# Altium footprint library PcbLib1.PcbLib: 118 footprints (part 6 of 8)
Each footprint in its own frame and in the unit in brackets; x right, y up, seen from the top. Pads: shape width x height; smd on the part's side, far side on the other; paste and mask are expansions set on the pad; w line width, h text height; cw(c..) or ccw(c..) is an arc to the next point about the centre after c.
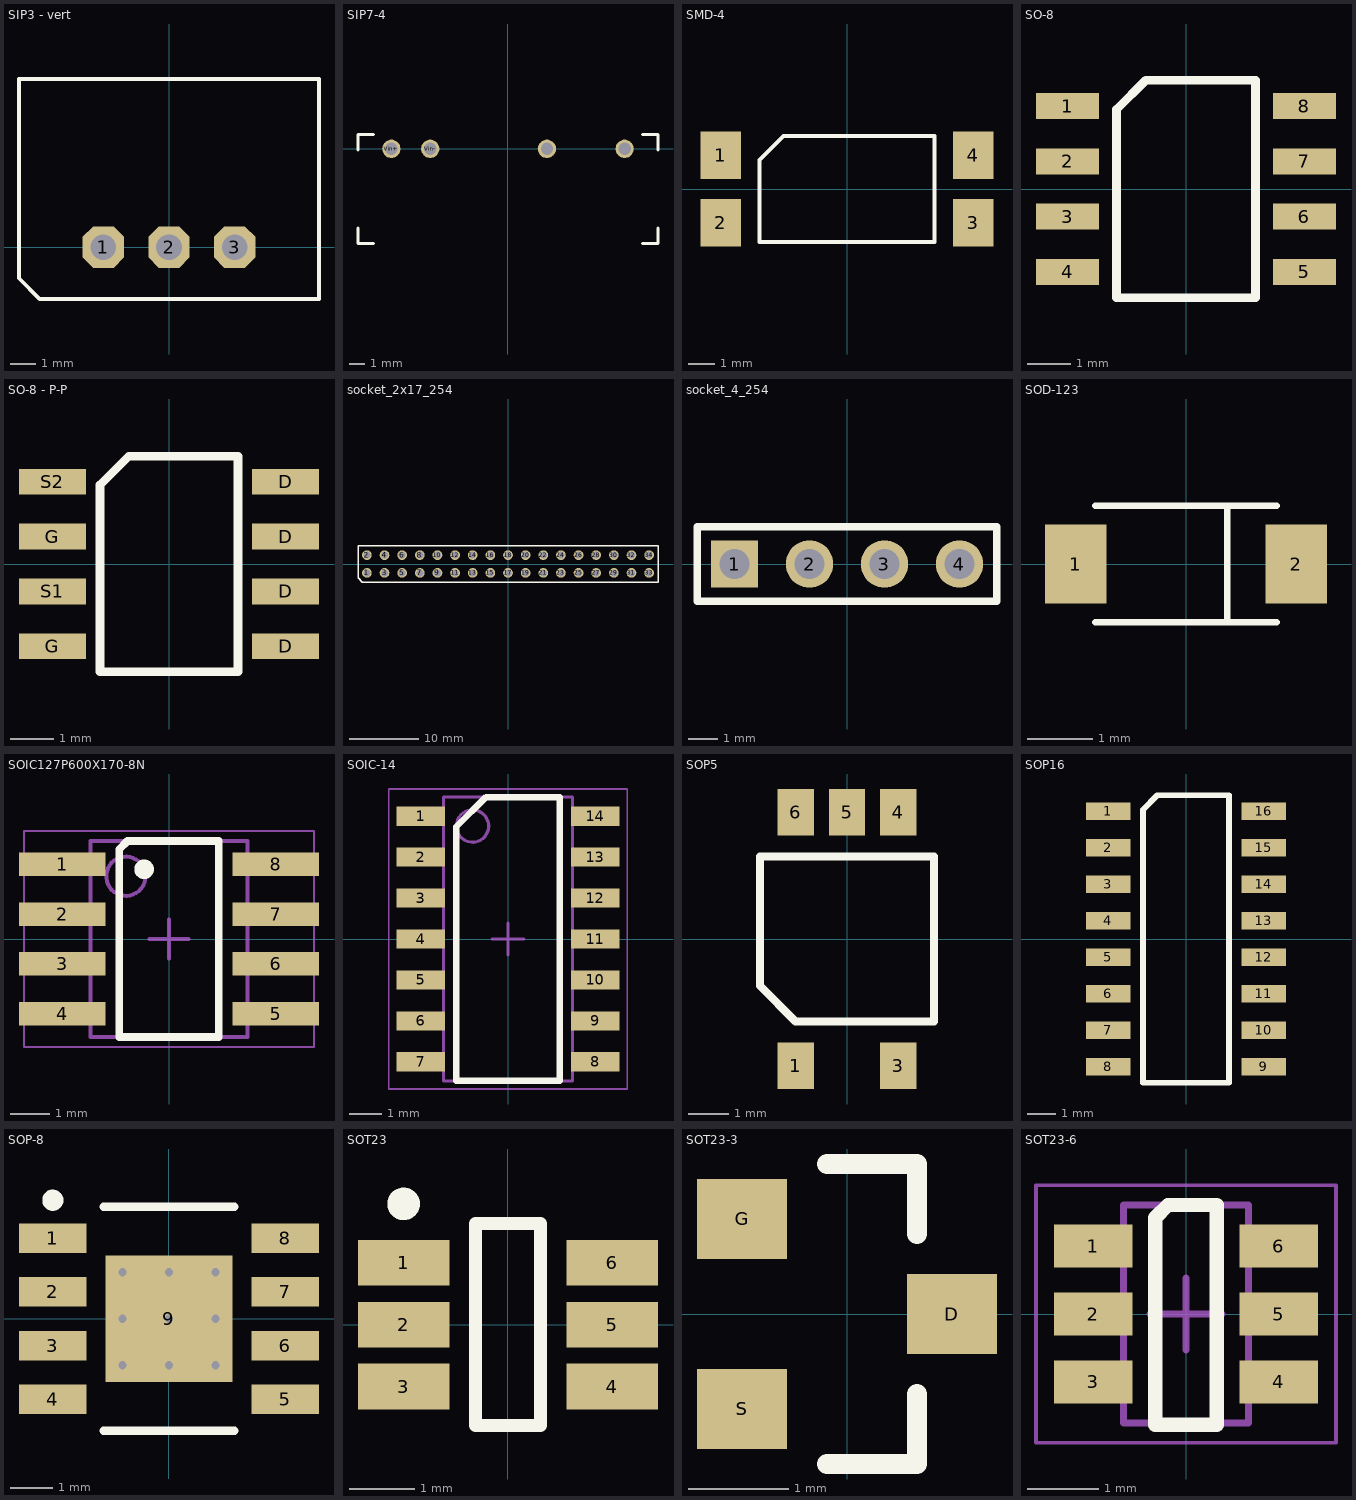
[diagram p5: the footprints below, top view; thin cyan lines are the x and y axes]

## SIP3 - vert [mm]
pads (3):
  oct 1.6x1.6 hole 1: 1(-2.54,0) 2(0,0) 3(2.54,0)
Top Overlay:
  lines w0.15: -5.8,-1.2 -5,-2 5.8,-2 5.8,6.5 -5.8,6.5 -5.8,-1.2
3D body "SIP3_vert.STEP": height 10.69, standoff -1.7, extent -5.8,-2 5.8,6.5

## SIP7-4 [mm] "4 pin SIP7 package"
pads (4):
  round 1.2 hole 0.8 mask+0.05: Vin+(-7.62,0) Vin-(-5.08,0) Vout+(7.62,0) Vout-(2.54,0)
Top Overlay:
  lines w0.2: -9.8,-5.175 -9.8,-6.175 -8.8,-6.175 ; -9.8,-0.075 -9.8,0.925 -8.8,0.925 ; 8.8,-6.175 9.8,-6.175 9.8,-5.175 ; 8.8,0.925 9.8,0.925 9.8,-0.075
3D body "SIP7-4.STEP": height 10.14, standoff -2.5, extent -9.8,-6.175 9.8,0.925

## SMD-4 [mm]
pads (4):
  rect 1.52x1.78 smd mask+0.08: 1(-4.765,1.27) 2(-4.765,-1.27) 3(4.765,-1.27) 4(4.765,1.27)
Top Overlay:
  lines w0.15: -3.3,-2 -3.3,1.1 -2.4,2 3.3,2 3.3,-2 -3.3,-2
3D body "PDIP-4_Gull_Wing.step": height 3.51, standoff 0.01, extent -5.08,-2.3 5.08,2.3

## SO-8 [mm] "SOIC, 8-Leads, Body 4,90x3,90mm, Pitch 1,27mm, IPC Medium Density"
height 1.75
pads (8):
  rect 1.45x0.6 smd: 1(-2.725,1.905) 2(-2.725,0.635) 3(-2.725,-0.635) 4(-2.725,-1.905) 5(2.725,-1.905) 6(2.725,-0.635) 7(2.725,0.635) 8(2.725,1.905)
Top Overlay:
  lines w0.2: -1.6,-2.5 -1.6,1.829 -0.929,2.5 1.6,2.5 1.6,-2.5 -1.6,-2.5
3D body "SO-8.step": height 1.75, standoff 0, extent -3,-2.5 3,2.5

## SO-8 - P-P [mm] "SO-8 push-pull FET"
height 1.75
pads (8):
  rect 1.55x0.6 smd: D(2.7,-1.905) D(2.7,-0.635) D(2.7,0.635) D(2.7,1.905) G(-2.7,-1.905) G(-2.7,0.635) S1(-2.7,-0.635) S2(-2.7,1.905)
Top Overlay:
  lines w0.2: -1.6,-2.5 -1.6,1.829 -0.929,2.5 1.6,2.5 1.6,-2.5 -1.6,-2.5
3D body "SO-8.step": height 1.75, standoff 0, extent -3,-2.5 3,2.5

## socket_2x17_254 [mm]
pads (34):
  round 1.4 hole 1: 1(-20.32,-1.27) 2(-20.32,1.27) 3(-17.78,-1.27) 4(-17.78,1.27) 5(-15.24,-1.27) 6(-15.24,1.27) 7(-12.7,-1.27) 8(-12.7,1.27) 9(-10.16,-1.27) 10(-10.16,1.27) 11(-7.62,-1.27) 12(-7.62,1.27) 13(-5.08,-1.27) 14(-5.08,1.27) 15(-2.54,-1.27) 16(-2.54,1.27) 17(0,-1.27) 18(0,1.27) 19(2.54,-1.27) 20(2.54,1.27) 21(5.08,-1.27) 22(5.08,1.27) 23(7.62,-1.27) 24(7.62,1.27) 25(10.16,-1.27) 26(10.16,1.27) 27(12.7,-1.27) 28(12.7,1.27) 29(15.24,-1.27) 30(15.24,1.27) 31(17.78,-1.27) 32(17.78,1.27) 33(20.32,-1.27) 34(20.32,1.27)
Top Overlay:
  lines w0.2: -21.6,-2 -21,-2.6 21.6,-2.6 21.6,2.6 -21.6,2.6 -21.6,-2

## socket_4_254 [mm]
pads (4):
  rect 1.6x1.6 hole 1: 1(-3.81,0)
  round 1.6 hole 1: 2(-1.27,0) 3(1.27,0) 4(3.81,0)
Top Overlay:
  lines w0.254: -5.08,-1.27 5.08,-1.27 5.08,1.27 -5.08,1.27 -5.08,-1.27
3D body "4pin_50mil_7mm.STEP": height 7.02, standoff -3.03, extent -5.33,-1.25 5.33,1.25

## SOD-123 [mm] "SODFL, 2-Leads, Body 1,60x3,75mm"
height 1.4
pads (2):
  rect 0.95x1.22 smd mask+0.03: 1(-1.7,0) 2(1.7,0)
Top Overlay:
  lines w0.1: -1.4,-0.9 1.4,-0.9 ; -1.4,0.9 1.4,0.9 ; 0.635,-0.9 0.635,0.889
3D body "SOD-123.step": height 1.4, standoff 0, extent -1.875,-0.9 1.875,0.9

## SOIC127P600X170-8N [mm] "SOIC, 8-Leads, Body 4,90x3,90mm, Pitch 1,27mm, IPC Medium Density"
height 1.7
pads (8):
  rect 2.2x0.6 smd: 1(-2.725,1.905) 2(-2.725,0.635) 3(-2.725,-0.635) 4(-2.725,-1.905) 5(2.725,-1.905) 6(2.725,-0.635) 7(2.725,0.635) 8(2.725,1.905)
Top Overlay:
  circle w0.3: c-0.635,1.778 r0.1
  lines w0.2: -1.27,-2.5 -1.27,2.286 -1.056,2.5 1.27,2.5 1.27,-2.5 -1.27,-2.5
Mechanical 13:
  circle w0.1: c-1.1,1.6 r0.5
  lines w0.1: -2,-2.5 2,-2.5 2,2.5 -2,2.5 -2,-2.5
Mechanical 15:
  lines w0.05: -3.7,-2.75 3.7,-2.75 3.7,2.75 -3.7,2.75 -3.7,-2.75
  lines w0.1: -0.5,0 0.5,0 ; 0,-0.5 0,0.5
3D body "SOIC127P600X170-8N.step": height 1.7, standoff 0, extent -3,-2.5 3,2.5

## SOIC-14 [mm] "SOIC-14, Pitch 1.27mm"
height 1.75
pads (14):
  rect 1.5x0.6 smd mask+0.03: 1(-2.7,3.81) 2(-2.7,2.54) 3(-2.7,1.27) 4(-2.7,0) 5(-2.7,-1.27) 6(-2.7,-2.54) 7(-2.7,-3.81) 8(2.7,-3.81) 9(2.7,-2.54) 10(2.7,-1.27) 11(2.7,0) 12(2.7,1.27) 13(2.7,2.54) 14(2.7,3.81)
Top Overlay:
  lines w0.2: -1.6,-4.4 1.6,-4.4 1.6,4.4 -0.68,4.4 -1.6,3.48 -1.6,-4.4
Mechanical 13:
  circle w0.1: c-1.1,3.5 r0.5
  lines w0.1: -2,-4.4 -2,4.4 2,4.4 2,-4.4 -2,-4.4
Mechanical 15:
  lines w0.05: -3.7,-4.65 -3.7,4.65 3.7,4.65 3.7,-4.65 -3.7,-4.65
  lines w0.1: -0.5,0 0.5,0 ; 0,-0.5 0,0.5
3D body "SOIC-14.step": height 1.75, standoff 0, extent -3,-4.4 3,4.4

## SOP5 [mm] "Small Outline; 6 Leads (1 Absent); Body Width 4.4 mm; Pitch 1.27 mm"
height 2.4
pads (5):
  rect 0.9x1.15 smd: 1(-1.27,-3.125) 3(1.27,-3.125) 4(1.27,3.125) 5(0,3.125) 6(-1.27,3.125)
Top Overlay:
  lines w0.2: -2.15,-1.152 -2.15,2.032 2.15,2.032 2.15,-2.032 -1.27,-2.032 -2.15,-1.152
3D body "SOP_5.STEP": height 2.23, standoff 0.03, extent -1.748,-3.475 1.952,3.475

## SOP16 [mm]
height 1.75
pads (16):
  rect 1.55x0.6 smd: 1(-2.7,4.445) 2(-2.7,3.175) 3(-2.7,1.905) 4(-2.7,0.635) 5(-2.7,-0.635) 6(-2.7,-1.905) 7(-2.7,-3.175) 8(-2.7,-4.445) 9(2.7,-4.445) 10(2.7,-3.175) 11(2.7,-1.905) 12(2.7,-0.635) 13(2.7,0.635) 14(2.7,1.905) 15(2.7,3.175) 16(2.7,4.445)
Top Overlay:
  lines w0.2: -1.5,-5 1.5,-5 1.5,5 -1,5 -1.5,4.5 -1.5,-5
3D body "SOP16.step": height 1.75, standoff 0, extent -3,-5 3,5

## SOP-8 [mm] "SOP, 8-Leads, Body 5,00x3,80mm, Pitch 1,27mm, Thermal Pad 3,00x3,00mm"
height 1.65
pads (9):
  rect 1.6x0.7 smd: 1(-2.75,1.905) 2(-2.75,0.635) 3(-2.75,-0.635) 4(-2.75,-1.905) 5(2.75,-1.905) 6(2.75,-0.635) 7(2.75,0.635) 8(2.75,1.905)
  rect 3x3 smd: 9(0,0)
via 1.1,-1.1 diameter 0.381 hole 0.2
via 0,-1.1 diameter 0.381 hole 0.2
via -1.1,-1.1 diameter 0.381 hole 0.2
via 1.1,0 diameter 0.381 hole 0.2
via 0,0 diameter 0.381 hole 0.2
via -1.1,0 diameter 0.381 hole 0.2
via 1.1,1.1 diameter 0.381 hole 0.2
via 0,1.1 diameter 0.381 hole 0.2
via -1.1,1.1 diameter 0.381 hole 0.2
Top Overlay:
  circle w0.25: c-2.75,2.805 r0.125
  region: -2.032,-0.381
  lines w0.2: -1.55,-2.65 1.55,-2.65 ; -1.55,2.65 1.55,2.65
3D body "SOP-8.step": height 1.65, standoff 0, extent -3,-2.65 3,2.65

## SOT23 [mm] "SOT23, 6-Leads, Body 2,90x3,10mm, Pitch 0,95mm, IPC Medium Density"
height 1.45
pads (6):
  rect 1.4x0.7 smd: 1(-1.6,0.95) 2(-1.6,0) 3(-1.6,-0.95) 4(1.6,-0.95) 5(1.6,0) 6(1.6,0.95)
Top Overlay:
  circle w0.25: c-1.6,1.85 r0.125
  lines w0.2: -0.5,-1.55 0.5,-1.55 0.5,1.55 -0.5,1.55 -0.5,-1.55
3D body "SOT23.step": height 1.45, standoff 0, extent -1.95,-1.55 1.95,1.55

## SOT23-3 [mm] "DMN6140LQ-7"
height 1.11
pads (3):
  rect 0.9x0.8 smd: D(1.05,0) G(-1.05,0.95) S(-1.05,-0.95)
Top Overlay:
  lines w0.2: -0.2,-1.5 0.7,-1.5 0.7,-0.8 ; -0.2,1.5 0.7,1.5 0.7,0.8
3D body "SOT23-3.step": height 1.11, standoff 0, extent -1.1,-1.52 1.1,1.52

## SOT23-6 [mm] "SOT23, 6-Leads, Pitch 0,95mm"
height 1.45
pads (6):
  rect 1.1x0.6 smd mask+0.03: 1(-1.3,0.95) 2(-1.3,0) 3(-1.3,-0.95) 4(1.3,-0.95) 5(1.3,0) 6(1.3,0.95)
Top Overlay:
  lines w0.2: -0.432,-1.55 -0.432,1.346 -0.253,1.525 0.432,1.525 0.432,-1.55 -0.432,-1.55
Mechanical 13:
  lines w0.1: -0.875,-1.525 0.875,-1.525 0.875,1.525 -0.875,1.525 -0.875,-1.525
Mechanical 15:
  lines w0.05: -2.1,-1.8 2.1,-1.8 2.1,1.8 -2.1,1.8 -2.1,-1.8
  lines w0.1: -0.5,0 0.5,0 ; 0,-0.5 0,0.5
3D body "SOT-23-6.step": height 1.45, standoff 0, extent -1.5,-1.525 1.5,1.525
